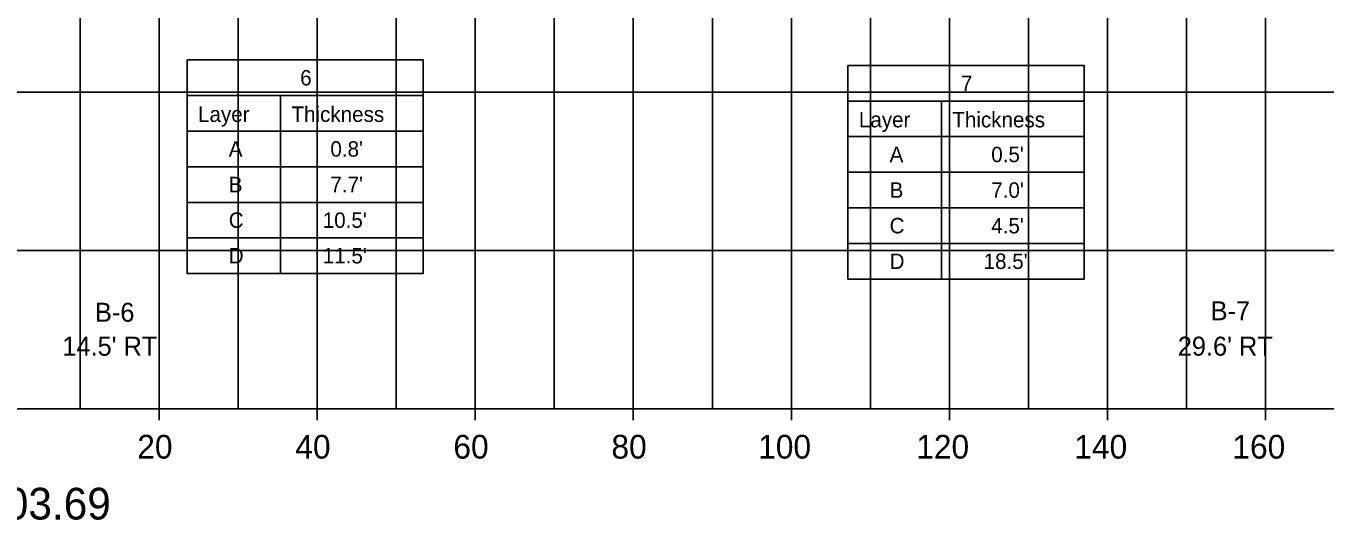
# Model space of a CAD drawing. Extents: x -290 to 297, y 616 to 861.
# Drawn here: x 3.2 to 167.5, y 615.9 to 678.4 of the extents above; entities that cross this region are included whole.
import ezdxf

# ---------------------------------------------------------------- set-up
doc = ezdxf.new("R2010")
doc.units = 0
for name, color, linetype in [('Cell', 7, 'Continuous'), ('DisROW Proposed Temp Easements', 7, 'Continuous'), ('SheetText', 7, 'Continuous'), ('TextAlignment', 7, 'Continuous'), ('TextAlignmentSml', 7, 'Continuous'), ('V-SWLK-CONC', 7, 'Continuous')]:
    doc.layers.add(name, color=color, linetype=linetype)

msp = doc.modelspace()

# ---------------------------------------------------------------- linework, layer by layer
at = {"layer": 'DisROW Proposed Temp Easements'}
for p, q in [((23.54, 669.59), (53.42, 669.59)), ((23.54, 647.09), (23.54, 669.59)), ((35.36, 669.59), (35.36, 647.09)), ((53.42, 669.59), (53.42, 647.09)), ((107.16, 668.9), (137.04, 668.9)), ((107.16, 646.4), (107.16, 668.9)), ((118.98, 668.9), (118.98, 646.4)), ((137.04, 668.9), (137.04, 646.4)), ((23.54, 665.09), (53.42, 665.09)), ((107.16, 664.4), (137.04, 664.4)), ((23.54, 660.59), (53.42, 660.59)), ((107.16, 659.9), (137.04, 659.9)), ((23.54, 656.09), (53.42, 656.09)), ((107.16, 655.4), (137.04, 655.4)), ((23.54, 651.59), (53.42, 651.59)), ((107.16, 650.9), (137.04, 650.9)), ((23.54, 647.09), (53.42, 647.09)), ((107.16, 646.4), (137.04, 646.4))]:
    msp.add_line(p, q, dxfattribs=at)
at = {"layer": 'SheetText'}
msp.add_line((-275.61, 630), (284.21, 630), dxfattribs=at)
at = {"layer": 'TextAlignment'}
for p, q in [((20, 630), (20, 787.99)), ((40, 630), (40, 787.99)), ((60, 630), (60, 787.99)), ((80, 630), (80, 787.99)), ((100, 630), (100, 787.99)), ((120, 630), (120, 787.99)), ((140, 630), (140, 787.99)), ((160, 630), (160, 787.99)), ((-275.61, 650), (284.21, 650)), ((20, 630), (20, 628.56)), ((40, 630), (40, 628.56)), ((60, 630), (60, 628.56)), ((80, 630), (80, 628.56)), ((100, 630), (100, 628.56)), ((120, 630), (120, 628.56)), ((140, 630), (140, 628.56)), ((160, 630), (160, 628.56))]:
    msp.add_line(p, q, dxfattribs=at)
at = {"layer": 'TextAlignmentSml'}
for p, q in [((10, 630), (10, 787.99)), ((30, 630), (30, 787.99)), ((50, 630), (50, 787.99)), ((70, 630), (70, 787.99)), ((90, 630), (90, 787.99)), ((110, 630), (110, 787.99)), ((130, 630), (130, 787.99)), ((150, 630), (150, 787.99)), ((-275.61, 670), (284.21, 670))]:
    msp.add_line(p, q, dxfattribs=at)
at = {"layer": 'V-SWLK-CONC'}
for points in [[(23.54, 674.09), (53.42, 674.09), (53.42, 669.59), (23.54, 669.59)], [(107.16, 673.4), (137.04, 673.4), (137.04, 668.9), (107.16, 668.9)], [(23.54, 669.59), (35.36, 669.59), (35.36, 665.09), (23.54, 665.09)], [(35.36, 669.59), (53.42, 669.59), (53.42, 665.09), (35.36, 665.09)], [(107.16, 668.9), (118.98, 668.9), (118.98, 664.4), (107.16, 664.4)], [(118.98, 668.9), (137.04, 668.9), (137.04, 664.4), (118.98, 664.4)], [(23.54, 665.09), (35.36, 665.09), (35.36, 660.59), (23.54, 660.59)], [(35.36, 665.09), (53.42, 665.09), (53.42, 660.59), (35.36, 660.59)], [(107.16, 664.4), (118.98, 664.4), (118.98, 659.9), (107.16, 659.9)], [(118.98, 664.4), (137.04, 664.4), (137.04, 659.9), (118.98, 659.9)], [(23.54, 660.59), (35.36, 660.59), (35.36, 656.09), (23.54, 656.09)], [(35.36, 660.59), (53.42, 660.59), (53.42, 656.09), (35.36, 656.09)], [(107.16, 659.9), (118.98, 659.9), (118.98, 655.4), (107.16, 655.4)], [(118.98, 659.9), (137.04, 659.9), (137.04, 655.4), (118.98, 655.4)], [(23.54, 656.09), (35.36, 656.09), (35.36, 651.59), (23.54, 651.59)], [(35.36, 656.09), (53.42, 656.09), (53.42, 651.59), (35.36, 651.59)], [(107.16, 655.4), (118.98, 655.4), (118.98, 650.9), (107.16, 650.9)], [(118.98, 655.4), (137.04, 655.4), (137.04, 650.9), (118.98, 650.9)], [(23.54, 651.59), (35.36, 651.59), (35.36, 647.09), (23.54, 647.09)], [(35.36, 651.59), (53.42, 651.59), (53.42, 647.09), (35.36, 647.09)], [(107.16, 650.9), (118.98, 650.9), (118.98, 646.4), (107.16, 646.4)], [(118.98, 650.9), (137.04, 650.9), (137.04, 646.4), (118.98, 646.4)]]:
    msp.add_lwpolyline(points, close=True, dxfattribs=at)

# ---------------------------------------------------------------- texts
at = {"layer": 'Cell'}
for s, height, p in [('20', 3, (17.23, 623.7)), ('40', 3, (37.23, 623.7)), ('60', 3, (57.23, 623.7)), ('80', 3, (77.23, 623.7)), ('100', 3, (95.8, 623.7)), ('120', 3, (115.8, 623.7)), ('140', 3, (135.8, 623.7)), ('160', 3, (155.8, 623.7)), ('STA 205+03.69', 4.008, (-23.51, 616))]:
    msp.add_text(s, height=height, dxfattribs=at).set_placement(p)
at = {"layer": 'DisROW Proposed Temp Easements'}
for s, p in [('6', (37.85, 670.87)), ('7', (121.46, 670.17)), ('Layer', (24.92, 666.26)), ('Thickness', (36.74, 666.26)), ('Layer', (108.54, 665.57)), ('Thickness', (120.36, 665.57)), ('A', (28.81, 661.87)), ("0.8'", (41.67, 661.87)), ('A', (112.43, 661.17)), ("0.5'", (125.29, 661.17)), ('B', (28.81, 657.37)), ("7.7'", (41.67, 657.37)), ('B', (112.43, 656.67)), ("7.0'", (125.29, 656.67)), ('C', (28.81, 652.87)), ("10.5'", (40.7, 652.87)), ('C', (112.43, 652.17)), ("4.5'", (125.29, 652.17)), ('D', (28.81, 648.37)), ("11.5'", (40.7, 648.37)), ('D', (112.43, 647.67)), ("18.5'", (124.32, 647.67))]:
    msp.add_text(s, height=1.95, dxfattribs=at).set_placement(p)
at = {"layer": 'V-SWLK-CONC'}
for s, p in [('B-6', (11.88, 641)), ('B-7', (153.05, 641.18)), ("14.5' RT", (7.75, 636.71)), ("29.6' RT", (148.89, 636.71))]:
    msp.add_text(s, height=2.4, dxfattribs=at).set_placement(p)

doc.saveas('drawing.dxf')
